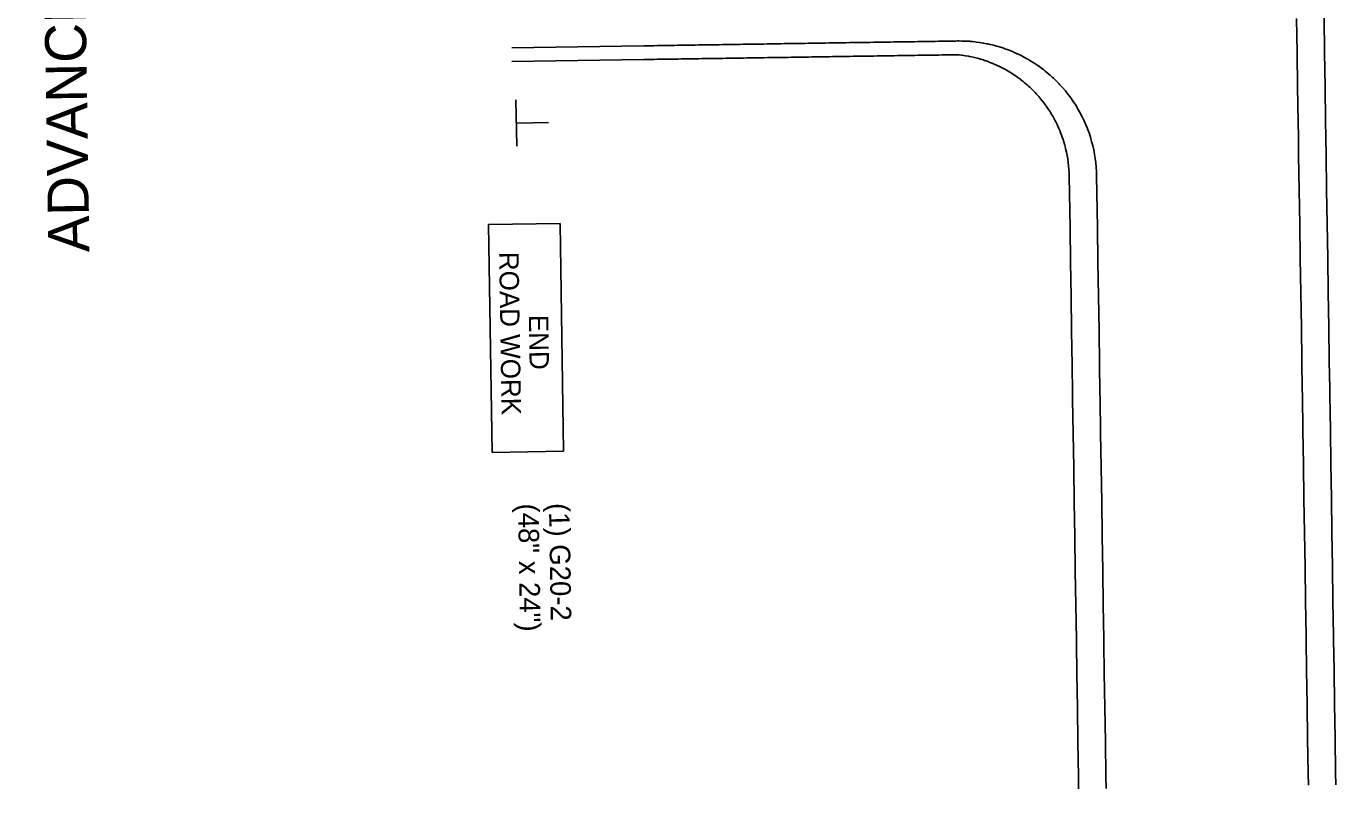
# Model space of a CAD drawing. Extents: x 1770018 to 1773492, y 718230 to 729141.
# Drawn here: x 1771495.6 to 1771877.5, y 720589.3 to 720811.7 of the extents above; entities that cross this region are included whole.
import ezdxf

# ---------------------------------------------------------------- set-up
doc = ezdxf.new("R2010")
doc.units = 0
for name, color, linetype in [('R_Draft', 7, 'Continuous'), ('R_MOT', 7, 'Continuous'), ('R_Proposed Road', 7, 'Continuous')]:
    doc.layers.add(name, color=color, linetype=linetype)

msp = doc.modelspace()

# ---------------------------------------------------------------- linework, layer by layer
at = {"layer": 'R_MOT'}
for p, q in [((1771638.67, 720776.74), (1771638.4, 720790.24)), ((1771638.73, 720783.46), (1771647.95, 720783.64)), ((1771630.46, 720753.86), (1771651.32, 720754.18)), ((1771631.48, 720687.45), (1771630.46, 720753.86)), ((1771652.34, 720687.77), (1771651.32, 720754.18)), ((1771631.48, 720687.45), (1771652.34, 720687.77))]:
    msp.add_line(p, q, dxfattribs=at)
at = {"layer": 'R_Proposed Road'}
for p, q in [((1771675.69, 720805.99), (1771637.2, 720805.39)), ((1771675.72, 720801.99), (1771637.26, 720801.39))]:
    msp.add_line(p, q, dxfattribs=at)
for points in [[(1771866.08, 720813.92), (1771866.23, 720803.92), (1771866.39, 720793.92), (1771866.54, 720783.92), (1771866.61, 720779.2), (1771866.61, 720779.19), (1771866.69, 720773.92), (1771866.85, 720763.93), (1771867, 720753.93), (1771867.16, 720743.93), (1771867.31, 720733.93), (1771867.47, 720723.93), (1771867.62, 720713.93), (1771867.74, 720705.95), (1771867.77, 720703.93), (1771867.93, 720693.93), (1771868.08, 720683.93), (1771868.24, 720673.94), (1771868.39, 720663.94), (1771868.54, 720653.94), (1771868.7, 720643.94), (1771868.85, 720633.94), (1771868.87, 720632.7), (1771869.01, 720623.94), (1771869.16, 720613.94), (1771869.31, 720603.94), (1771869.47, 720593.95), (1771869.52, 720590.38)], [(1771874.08, 720814.04), (1771874.23, 720804.04), (1771874.39, 720794.05), (1771874.54, 720784.05), (1771874.61, 720779.32), (1771874.61, 720779.32), (1771874.69, 720774.05), (1771874.85, 720764.05), (1771875, 720754.05), (1771875.16, 720744.05), (1771875.31, 720734.05), (1771875.46, 720724.05), (1771875.62, 720714.05), (1771875.74, 720706.07), (1771875.77, 720704.06), (1771875.93, 720694.06), (1771876.08, 720684.06), (1771876.23, 720674.06), (1771876.39, 720664.06), (1771876.54, 720654.06), (1771876.7, 720644.06), (1771876.85, 720634.06), (1771876.87, 720632.82), (1771877, 720624.07), (1771877.16, 720614.07), (1771877.31, 720604.07), (1771877.47, 720594.07), (1771877.52, 720590.5)], [(1771807.78, 720768.02), (1771807.74, 720769.3), (1771807.66, 720770.58), (1771807.53, 720771.85), (1771807.37, 720773.13), (1771807.18, 720774.31), (1771807.17, 720774.39), (1771806.92, 720775.65), (1771806.64, 720776.9), (1771806.31, 720778.14), (1771806.11, 720778.84), (1771805.95, 720779.37), (1771805.55, 720780.59), (1771805.11, 720781.79), (1771805.06, 720781.9), (1771804.62, 720782.98), (1771804.11, 720784.15), (1771804.03, 720784.32), (1771803.55, 720785.31), (1771803, 720786.38), (1771802.96, 720786.45), (1771802.33, 720787.56), (1771801.97, 720788.17), (1771801.67, 720788.66), (1771800.97, 720789.74), (1771800.94, 720789.77), (1771800.23, 720790.79), (1771799.92, 720791.22), (1771799.47, 720791.82), (1771798.9, 720792.53), (1771798.67, 720792.82), (1771797.88, 720793.75), (1771797.84, 720793.8), (1771796.98, 720794.74), (1771796.86, 720794.86), (1771796.09, 720795.67), (1771795.85, 720795.9), (1771795.63, 720796.12), (1771795.16, 720796.56), (1771794.83, 720796.87), (1771794.22, 720797.42), (1771793.82, 720797.77), (1771793.24, 720798.25), (1771792.81, 720798.61), (1771792.24, 720799.05), (1771791.79, 720799.39), (1771791.21, 720799.82), (1771790.78, 720800.13), (1771790.16, 720800.56), (1771789.77, 720800.81), (1771789.09, 720801.26), (1771788.76, 720801.46), (1771787.99, 720801.92), (1771787.75, 720802.06), (1771787.25, 720802.34), (1771786.87, 720802.55), (1771786.74, 720802.62), (1771785.74, 720803.14), (1771785.74, 720803.15), (1771784.73, 720803.63), (1771784.58, 720803.7), (1771783.72, 720804.09), (1771783.41, 720804.22), (1771782.71, 720804.51), (1771782.22, 720804.7), (1771781.71, 720804.9), (1771781.02, 720805.15), (1771780.7, 720805.26), (1771779.8, 720805.55), (1771779.7, 720805.58), (1771778.69, 720805.88), (1771778.57, 720805.92), (1771777.69, 720806.15), (1771777.33, 720806.24), (1771776.68, 720806.4), (1771776.08, 720806.53), (1771775.68, 720806.61), (1771774.82, 720806.78), (1771774.68, 720806.8), (1771773.67, 720806.96), (1771773.56, 720806.98), (1771772.67, 720807.1), (1771772.29, 720807.15), (1771771.67, 720807.21), (1771771.01, 720807.27), (1771770.67, 720807.3), (1771769.73, 720807.35), (1771769.67, 720807.36), (1771768.67, 720807.39), (1771768.45, 720807.39), (1771767.67, 720807.4), (1771767.17, 720807.4), (1771766.67, 720807.39), (1771765.67, 720807.37), (1771764.67, 720807.36), (1771763.67, 720807.34), (1771762.67, 720807.33), (1771761.67, 720807.31), (1771760.67, 720807.29), (1771759.67, 720807.28), (1771758.67, 720807.26), (1771757.67, 720807.25), (1771756.67, 720807.23), (1771755.67, 720807.22), (1771754.67, 720807.2), (1771753.67, 720807.19), (1771752.67, 720807.17), (1771751.67, 720807.16), (1771750.67, 720807.14), (1771749.67, 720807.13), (1771748.67, 720807.11), (1771747.67, 720807.09), (1771746.67, 720807.08), (1771745.67, 720807.06), (1771744.67, 720807.05), (1771743.67, 720807.03), (1771742.67, 720807.02), (1771741.67, 720807), (1771740.67, 720806.99), (1771739.67, 720806.97), (1771738.67, 720806.96), (1771737.67, 720806.94), (1771736.67, 720806.93), (1771735.67, 720806.91), (1771734.67, 720806.89), (1771733.67, 720806.88), (1771732.67, 720806.86), (1771731.67, 720806.85), (1771730.67, 720806.83), (1771729.67, 720806.82), (1771728.67, 720806.8), (1771727.67, 720806.79), (1771726.67, 720806.77), (1771725.67, 720806.76), (1771724.67, 720806.74), (1771723.67, 720806.72), (1771722.67, 720806.71), (1771721.67, 720806.69), (1771720.67, 720806.68), (1771719.67, 720806.66), (1771718.67, 720806.65), (1771717.67, 720806.63), (1771716.67, 720806.62), (1771715.67, 720806.6), (1771714.67, 720806.59), (1771713.67, 720806.57), (1771712.67, 720806.56), (1771711.67, 720806.54), (1771710.67, 720806.52), (1771709.67, 720806.51), (1771708.67, 720806.49), (1771707.67, 720806.48), (1771706.67, 720806.46), (1771705.67, 720806.45), (1771704.67, 720806.43), (1771703.67, 720806.42), (1771702.67, 720806.4), (1771701.68, 720806.39), (1771700.68, 720806.37), (1771699.68, 720806.36), (1771698.68, 720806.34), (1771697.68, 720806.32), (1771696.68, 720806.31), (1771695.68, 720806.29), (1771694.68, 720806.28), (1771693.68, 720806.26), (1771692.68, 720806.25), (1771691.68, 720806.23), (1771690.68, 720806.22), (1771689.68, 720806.2), (1771688.68, 720806.19), (1771687.68, 720806.17), (1771687.18, 720806.16), (1771686.68, 720806.15), (1771685.68, 720806.14), (1771684.68, 720806.12), (1771683.68, 720806.11), (1771682.68, 720806.09), (1771681.68, 720806.08), (1771680.68, 720806.06), (1771679.68, 720806.05), (1771678.68, 720806.03), (1771677.95, 720806.02), (1771677.68, 720806.02), (1771676.67, 720806), (1771675.69, 720805.99)], [(1771799.78, 720767.89), (1771799.75, 720768.92), (1771799.69, 720769.94), (1771799.6, 720770.96), (1771799.49, 720771.98), (1771799.35, 720772.94), (1771799.34, 720773), (1771799.17, 720774.02), (1771798.97, 720775.02), (1771798.73, 720776.03), (1771798.59, 720776.6), (1771798.47, 720777.03), (1771798.19, 720778.02), (1771797.87, 720779), (1771797.84, 720779.09), (1771797.53, 720779.98), (1771797.15, 720780.95), (1771797.1, 720781.09), (1771796.75, 720781.9), (1771796.35, 720782.79), (1771796.32, 720782.85), (1771795.87, 720783.79), (1771795.6, 720784.3), (1771795.38, 720784.72), (1771794.87, 720785.63), (1771794.85, 720785.66), (1771794.33, 720786.53), (1771794.1, 720786.9), (1771793.76, 720787.42), (1771793.34, 720788.04), (1771793.17, 720788.29), (1771792.58, 720789.1), (1771792.54, 720789.15), (1771791.9, 720789.99), (1771791.81, 720790.09), (1771791.22, 720790.81), (1771791.04, 720791.02), (1771790.88, 720791.21), (1771790.52, 720791.61), (1771790.27, 720791.89), (1771789.8, 720792.4), (1771789.49, 720792.72), (1771789.04, 720793.17), (1771788.71, 720793.5), (1771788.27, 720793.91), (1771787.92, 720794.23), (1771787.47, 720794.64), (1771787.13, 720794.93), (1771786.64, 720795.34), (1771786.34, 720795.59), (1771785.79, 720796.02), (1771785.54, 720796.22), (1771784.92, 720796.68), (1771784.73, 720796.82), (1771784.33, 720797.1), (1771784.03, 720797.31), (1771783.92, 720797.38), (1771783.11, 720797.92), (1771783.11, 720797.92), (1771782.29, 720798.43), (1771782.17, 720798.5), (1771781.47, 720798.91), (1771781.21, 720799.05), (1771780.64, 720799.36), (1771780.24, 720799.57), (1771779.81, 720799.79), (1771779.24, 720800.07), (1771778.97, 720800.19), (1771778.22, 720800.53), (1771778.13, 720800.57), (1771777.29, 720800.93), (1771777.19, 720800.97), (1771776.44, 720801.26), (1771776.14, 720801.37), (1771775.58, 720801.57), (1771775.07, 720801.75), (1771774.72, 720801.86), (1771773.99, 720802.09), (1771773.86, 720802.12), (1771772.99, 720802.36), (1771772.89, 720802.39), (1771772.12, 720802.58), (1771771.78, 720802.66), (1771771.24, 720802.78), (1771770.66, 720802.9), (1771770.36, 720802.96), (1771769.52, 720803.1), (1771769.47, 720803.11), (1771768.58, 720803.24), (1771768.38, 720803.27), (1771767.68, 720803.35), (1771767.23, 720803.4), (1771766.73, 720803.39), (1771765.73, 720803.37), (1771764.73, 720803.36), (1771763.73, 720803.34), (1771762.73, 720803.33), (1771761.73, 720803.31), (1771760.73, 720803.3), (1771759.73, 720803.28), (1771758.73, 720803.26), (1771757.73, 720803.25), (1771756.73, 720803.23), (1771755.73, 720803.22), (1771754.73, 720803.2), (1771753.73, 720803.19), (1771752.73, 720803.17), (1771751.73, 720803.16), (1771750.73, 720803.14), (1771749.73, 720803.13), (1771748.73, 720803.11), (1771747.73, 720803.1), (1771746.73, 720803.08), (1771745.73, 720803.06), (1771744.73, 720803.05), (1771743.73, 720803.03), (1771742.73, 720803.02), (1771741.73, 720803), (1771740.73, 720802.99), (1771739.73, 720802.97), (1771738.73, 720802.96), (1771737.73, 720802.94), (1771736.73, 720802.93), (1771735.73, 720802.91), (1771734.73, 720802.89), (1771733.73, 720802.88), (1771732.73, 720802.86), (1771731.73, 720802.85), (1771730.73, 720802.83), (1771729.73, 720802.82), (1771728.73, 720802.8), (1771727.73, 720802.79), (1771726.73, 720802.77), (1771725.73, 720802.76), (1771724.73, 720802.74), (1771723.73, 720802.73), (1771722.73, 720802.71), (1771721.73, 720802.69), (1771720.73, 720802.68), (1771719.73, 720802.66), (1771718.73, 720802.65), (1771717.73, 720802.63), (1771716.73, 720802.62), (1771715.74, 720802.6), (1771714.74, 720802.59), (1771713.74, 720802.57), (1771712.74, 720802.56), (1771711.74, 720802.54), (1771710.74, 720802.53), (1771709.74, 720802.51), (1771708.74, 720802.49), (1771707.74, 720802.48), (1771706.74, 720802.46), (1771705.74, 720802.45), (1771704.74, 720802.43), (1771703.74, 720802.42), (1771702.74, 720802.4), (1771701.74, 720802.39), (1771700.74, 720802.37), (1771699.74, 720802.36), (1771698.74, 720802.34), (1771697.74, 720802.32), (1771696.74, 720802.31), (1771695.74, 720802.29), (1771694.74, 720802.28), (1771693.74, 720802.26), (1771692.74, 720802.25), (1771691.74, 720802.23), (1771690.74, 720802.22), (1771689.74, 720802.2), (1771688.74, 720802.19), (1771687.74, 720802.17), (1771687.24, 720802.16), (1771686.74, 720802.16), (1771685.74, 720802.14), (1771684.74, 720802.12), (1771683.74, 720802.11), (1771682.74, 720802.09), (1771681.74, 720802.08), (1771680.74, 720802.06), (1771679.74, 720802.05), (1771678.74, 720802.03), (1771678.01, 720802.02), (1771677.74, 720802.02), (1771676.73, 720802), (1771675.75, 720801.99)], [(1771799.78, 720767.89), (1771799.86, 720762.89), (1771800.01, 720752.89), (1771800.16, 720742.9), (1771800.32, 720732.9), (1771800.47, 720722.9), (1771800.63, 720712.9), (1771800.75, 720704.92), (1771800.78, 720702.9), (1771800.94, 720692.9), (1771801.09, 720682.9), (1771801.24, 720672.9), (1771801.4, 720662.91), (1771801.55, 720652.91), (1771801.71, 720642.91), (1771801.86, 720632.91), (1771801.88, 720631.67), (1771802.01, 720622.91), (1771802.17, 720612.91), (1771802.32, 720602.91), (1771802.48, 720592.91), (1771802.53, 720589.35)], [(1771807.78, 720768.02), (1771807.86, 720763.02), (1771808.01, 720753.02), (1771808.16, 720743.02), (1771808.32, 720733.02), (1771808.47, 720723.02), (1771808.63, 720713.02), (1771808.75, 720705.04), (1771808.78, 720703.02), (1771808.93, 720693.02), (1771809.09, 720683.03), (1771809.24, 720673.03), (1771809.4, 720663.03), (1771809.55, 720653.03), (1771809.7, 720643.03), (1771809.86, 720633.03), (1771809.88, 720631.79), (1771810.01, 720623.03), (1771810.17, 720613.03), (1771810.32, 720603.04), (1771810.47, 720593.04), (1771810.53, 720589.47)]]:
    msp.add_lwpolyline(points, dxfattribs=at)

# ---------------------------------------------------------------- texts
at = {"layer": 'R_Draft'}
msp.add_text('ADVANCE WARNING HWY. 230 (STAGES 1, 2, & 3)', height=12, rotation=90.8827, dxfattribs=at).set_placement((1771514.06, 720745.83))
at = {"layer": 'R_MOT'}
for s, height, p in [('ROAD WORK', 5.67, (1771633.52, 720745.87)), ('END', 5.67, (1771642.18, 720727.5)), ('(48" x 24")', 5.9994, (1771639.05, 720672.49)), ('(1) G20-2', 6, (1771648.05, 720672.63))]:
    msp.add_text(s, height=height, rotation=270.8827, dxfattribs=at).set_placement(p)

doc.saveas('drawing.dxf')
